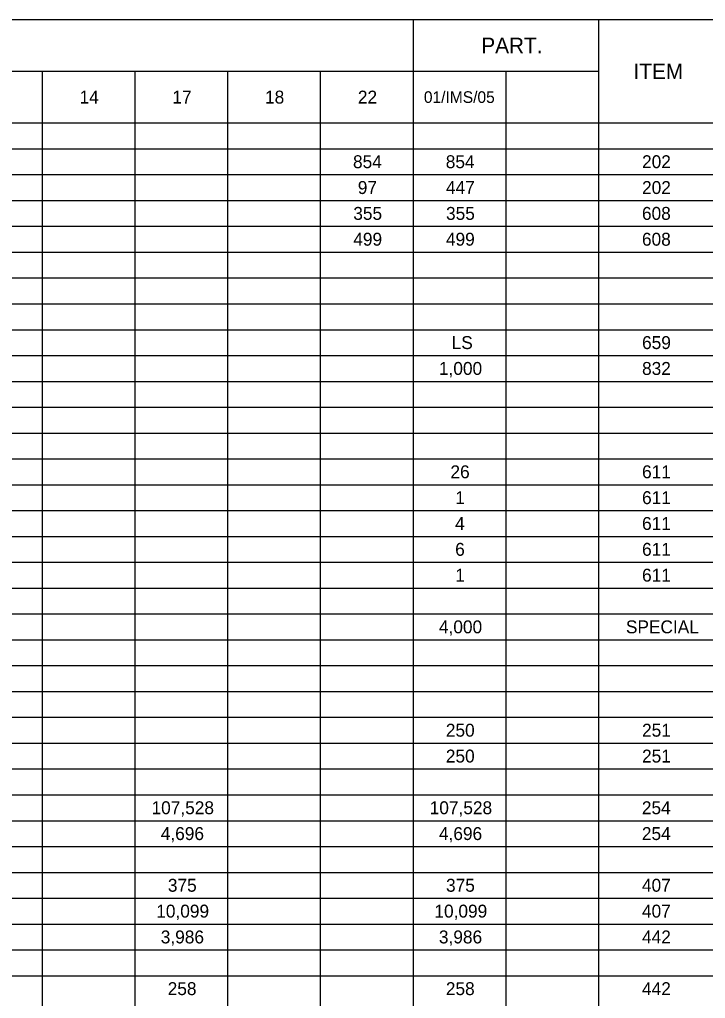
# Model space of a CAD drawing. Extents: x -32.9 to 34, y 0 to 22.
# Drawn here: x -25.15 to -17.72, y 10.89 to 21.5 of the extents above; entities that cross this region are included whole.
import ezdxf

# ---------------------------------------------------------------- set-up
doc = ezdxf.new("R2010")
doc.units = 0
doc.layers.add('SH_Text', color=7, linetype='Continuous')

msp = doc.modelspace()

# ---------------------------------------------------------------- linework, layer by layer
at = {"layer": 'SH_Text'}
for p, q in [((-32.943, 21.5), (-2.439, 21.5)), ((-20.886, 21.5), (-20.886, 0.5)), ((-18.877, 21.5), (-18.877, 0.5)), ((-32.943, 20.94), (-18.877, 20.94)), ((-24.905, 20.94), (-24.905, 0.5)), ((-23.9, 20.94), (-23.9, 0.5)), ((-22.896, 20.94), (-22.896, 0.5)), ((-21.891, 20.94), (-21.891, 0.5)), ((-19.882, 20.94), (-19.882, 0.5)), ((-32.943, 20.38), (-2.439, 20.38)), ((-32.943, 20.1), (-2.439, 20.1)), ((-32.943, 19.82), (-2.439, 19.82)), ((-32.943, 19.54), (-2.439, 19.54)), ((-32.943, 19.26), (-2.439, 19.26)), ((-32.943, 18.98), (-2.439, 18.98)), ((-32.943, 18.7), (-2.439, 18.7)), ((-32.943, 18.42), (-2.439, 18.42)), ((-32.943, 18.14), (-2.439, 18.14)), ((-32.943, 17.86), (-2.439, 17.86)), ((-32.943, 17.58), (-2.439, 17.58)), ((-32.943, 17.3), (-2.439, 17.3)), ((-32.943, 17.02), (-2.439, 17.02)), ((-32.943, 16.74), (-2.439, 16.74)), ((-32.943, 16.46), (-2.439, 16.46)), ((-32.943, 16.18), (-2.439, 16.18)), ((-32.943, 15.9), (-2.439, 15.9)), ((-32.943, 15.62), (-2.439, 15.62)), ((-32.943, 15.34), (-2.439, 15.34)), ((-32.943, 15.06), (-2.439, 15.06)), ((-32.943, 14.78), (-2.439, 14.78)), ((-32.943, 14.5), (-2.439, 14.5)), ((-32.943, 14.22), (-2.439, 14.22)), ((-32.943, 13.94), (-2.439, 13.94)), ((-32.943, 13.66), (-2.439, 13.66)), ((-32.943, 13.38), (-2.439, 13.38)), ((-32.943, 13.1), (-2.439, 13.1)), ((-32.943, 12.82), (-2.439, 12.82)), ((-32.943, 12.54), (-2.439, 12.54)), ((-32.943, 12.26), (-2.439, 12.26)), ((-32.943, 11.98), (-2.439, 11.98)), ((-32.943, 11.7), (-2.439, 11.7)), ((-32.943, 11.42), (-2.439, 11.42)), ((-32.943, 11.14), (-2.439, 11.14))]:
    msp.add_line(p, q, dxfattribs=at)

# ---------------------------------------------------------------- texts
for s, height, p in [('PART.', 0.168, (-20.146, 21.136)), ('ITEM', 0.168, (-18.497, 20.856)), ('14', 0.14, (-24.5, 20.59)), ('17', 0.14, (-23.494, 20.59)), ('18', 0.14, (-22.49, 20.59)), ('22', 0.14, (-21.484, 20.59)), ('01/IMS/05', 0.126, (-20.769, 20.597)), ('854', 0.14, (-21.537, 19.89)), ('854', 0.14, (-20.532, 19.89)), ('202', 0.14, (-18.405, 19.89)), ('97', 0.14, (-21.485, 19.61)), ('447', 0.14, (-20.53, 19.61)), ('202', 0.14, (-18.405, 19.61)), ('355', 0.14, (-21.534, 19.33)), ('355', 0.14, (-20.529, 19.33)), ('608', 0.14, (-18.406, 19.33)), ('499', 0.14, (-21.534, 19.05)), ('499', 0.14, (-20.53, 19.05)), ('608', 0.14, (-18.406, 19.05)), ('LS', 0.14, (-20.468, 17.93)), ('659', 0.14, (-18.405, 17.93)), ('1,000', 0.14, (-20.606, 17.65)), ('832', 0.14, (-18.405, 17.65)), ('26', 0.14, (-20.481, 16.53)), ('611', 0.14, (-18.405, 16.53)), ('1', 0.14, (-20.429, 16.25)), ('611', 0.14, (-18.405, 16.25)), ('4', 0.14, (-20.431, 15.97)), ('611', 0.14, (-18.405, 15.97)), ('6', 0.14, (-20.43, 15.69)), ('611', 0.14, (-18.405, 15.69)), ('1', 0.14, (-20.429, 15.41)), ('611', 0.14, (-18.405, 15.41)), ('4,000', 0.14, (-20.606, 14.85)), ('SPECIAL', 0.14, (-18.58, 14.85)), ('250', 0.14, (-20.531, 13.73)), ('251', 0.14, (-18.405, 13.73)), ('250', 0.14, (-20.531, 13.45)), ('251', 0.14, (-18.405, 13.45)), ('107,528', 0.14, (-23.72, 12.89)), ('107,528', 0.14, (-20.706, 12.89)), ('254', 0.14, (-18.407, 12.89)), ('4,696', 0.14, (-23.62, 12.61)), ('4,696', 0.14, (-20.606, 12.61)), ('254', 0.14, (-18.407, 12.61)), ('375', 0.14, (-23.543, 12.05)), ('375', 0.14, (-20.529, 12.05)), ('407', 0.14, (-18.406, 12.05)), ('10,099', 0.14, (-23.669, 11.77)), ('10,099', 0.14, (-20.655, 11.77)), ('407', 0.14, (-18.406, 11.77)), ('3,986', 0.14, (-23.62, 11.49)), ('3,986', 0.14, (-20.606, 11.49)), ('442', 0.14, (-18.405, 11.49)), ('258', 0.14, (-23.545, 10.93)), ('258', 0.14, (-20.531, 10.93)), ('442', 0.14, (-18.405, 10.93))]:
    msp.add_text(s, height=height, dxfattribs=at).set_placement(p)

doc.saveas('drawing.dxf')
